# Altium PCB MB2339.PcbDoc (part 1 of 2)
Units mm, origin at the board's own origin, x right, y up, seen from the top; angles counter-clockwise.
Board outline 43 x 47 mm, 4 copper layers (Top Layer, Signal Layer 1, Signal Layer 2, Bottom Layer), stack 1.539 mm thick; 100 components, 80 nets, 370 pads, 542 vias.
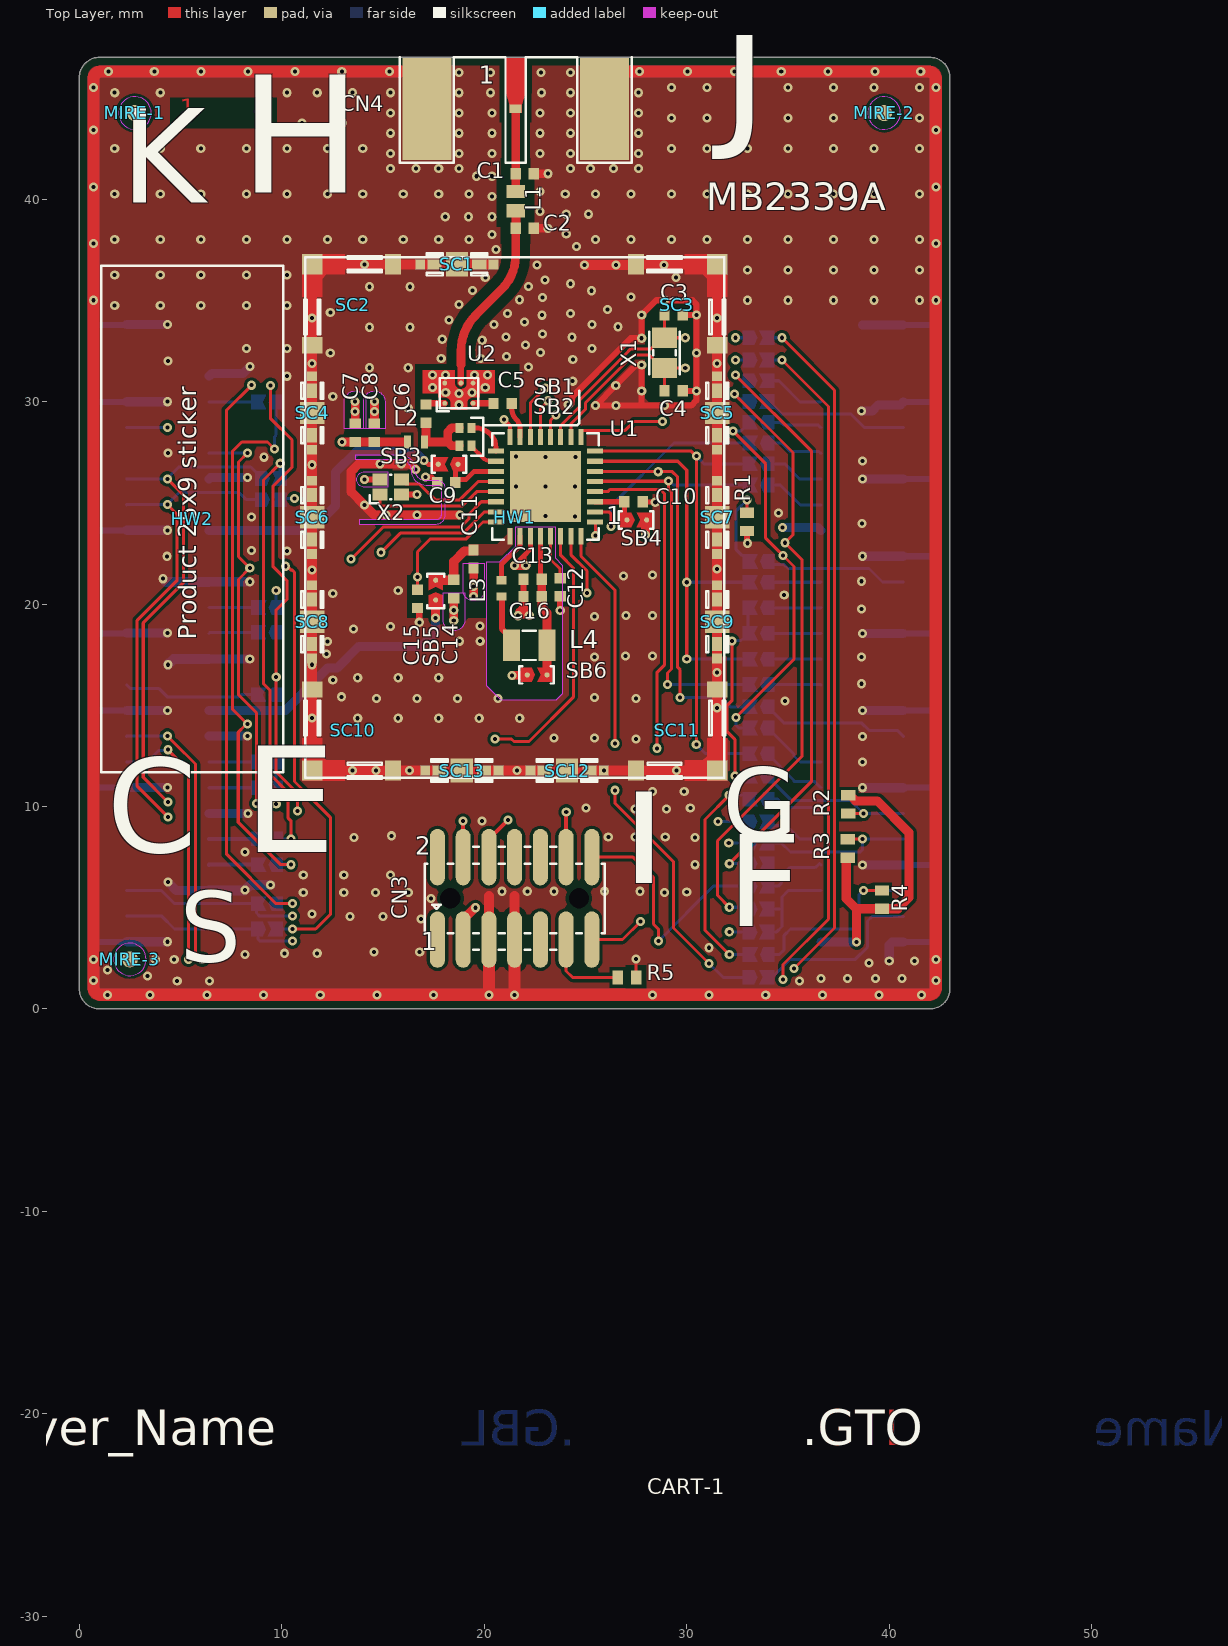
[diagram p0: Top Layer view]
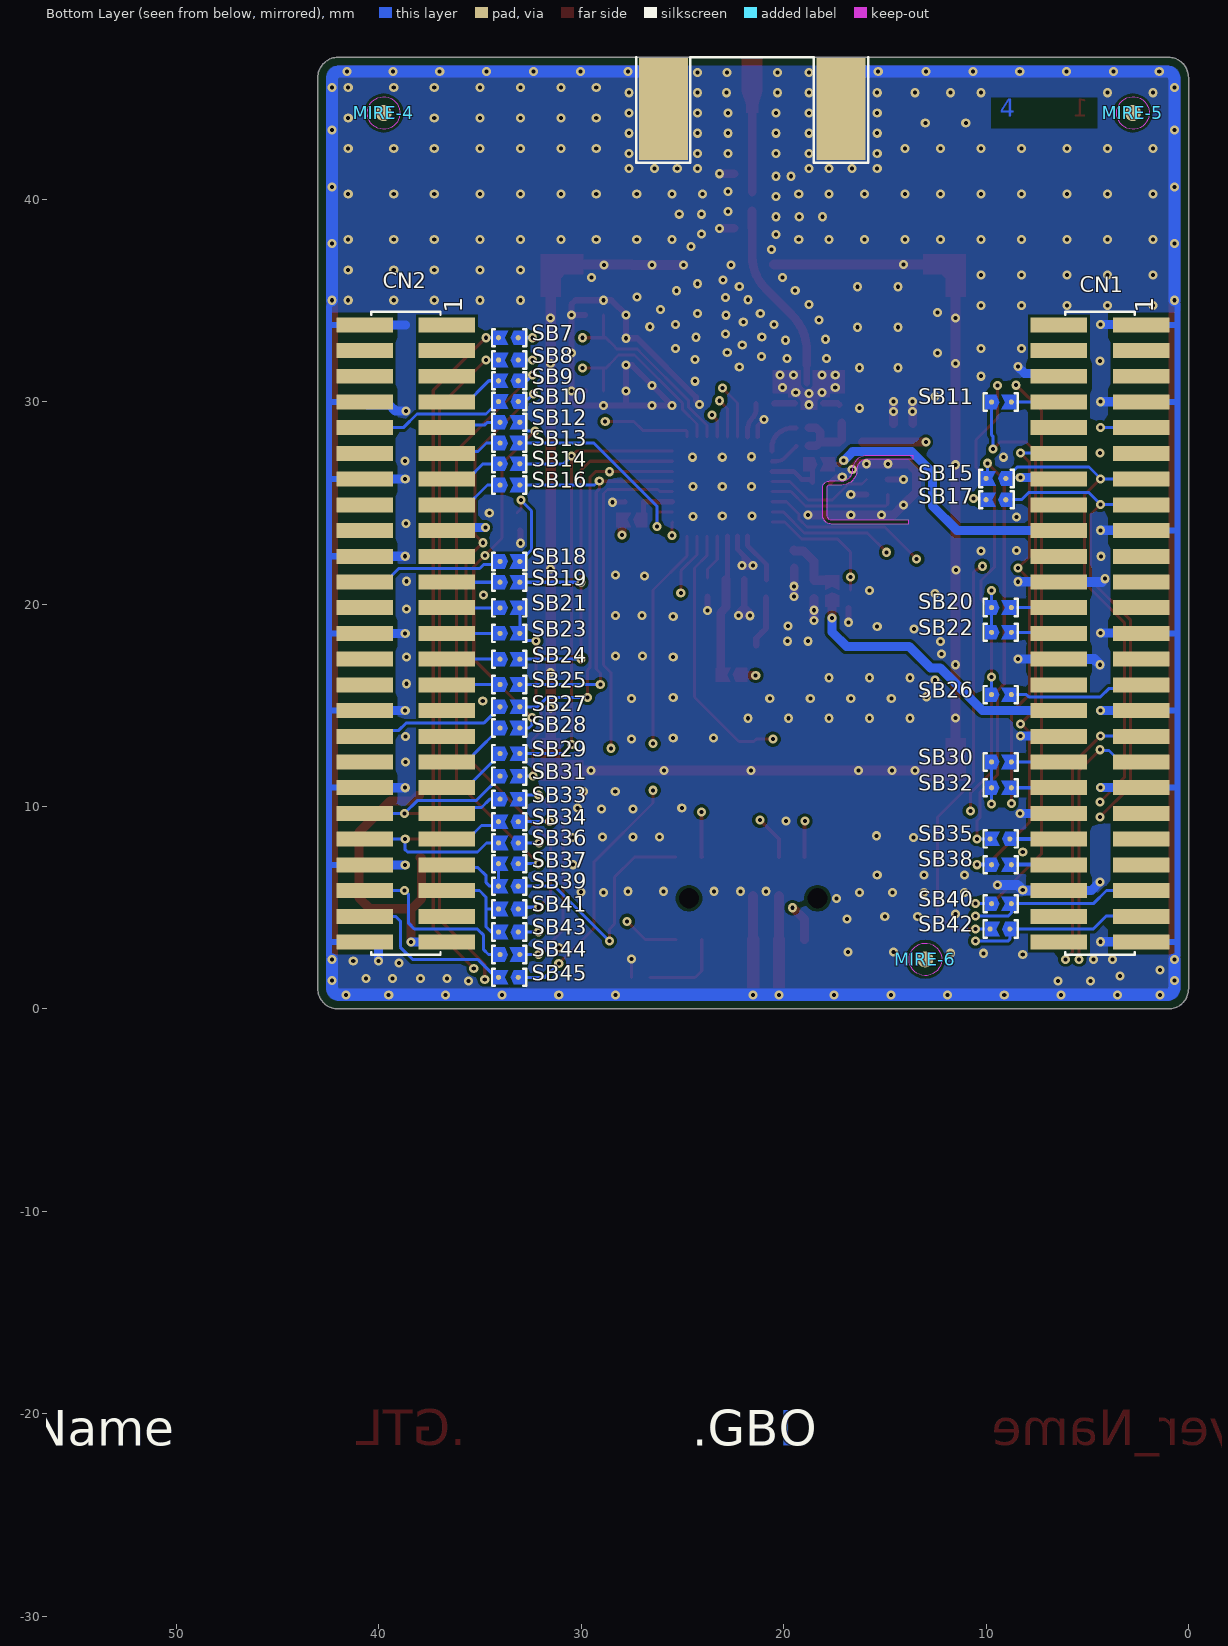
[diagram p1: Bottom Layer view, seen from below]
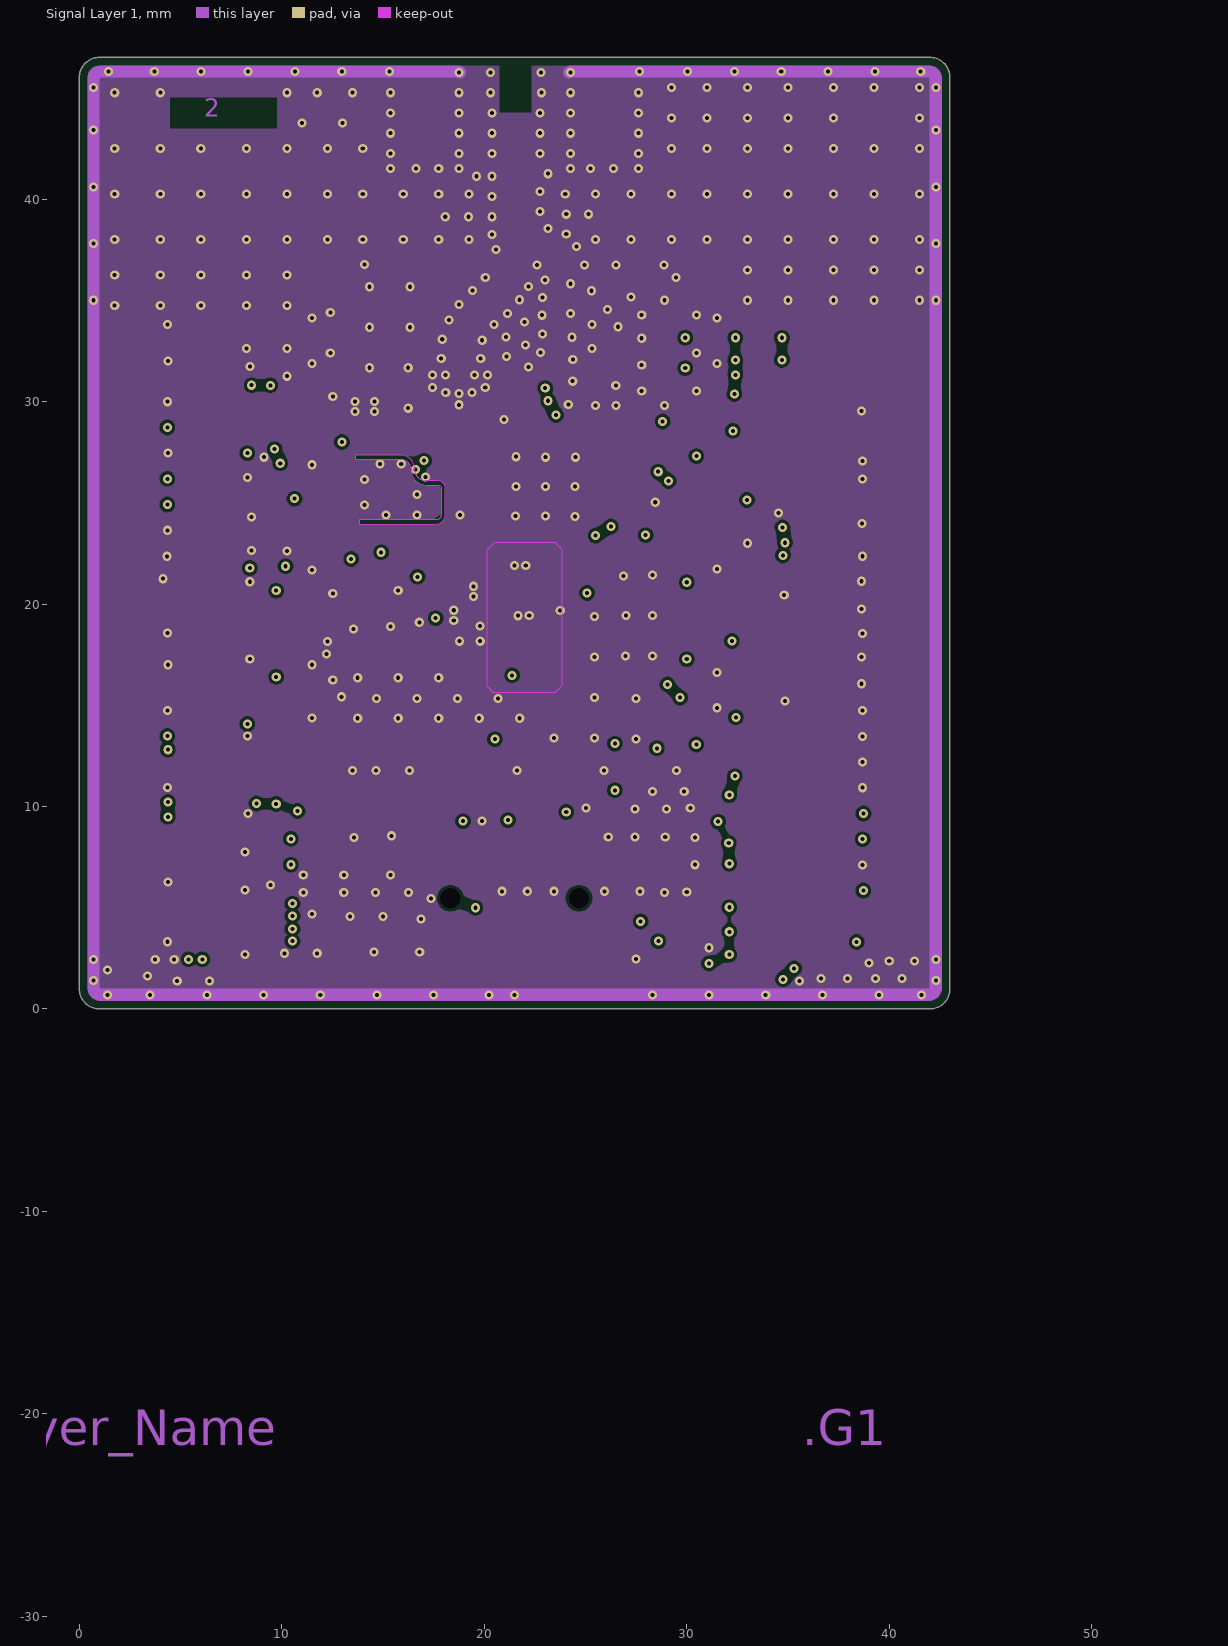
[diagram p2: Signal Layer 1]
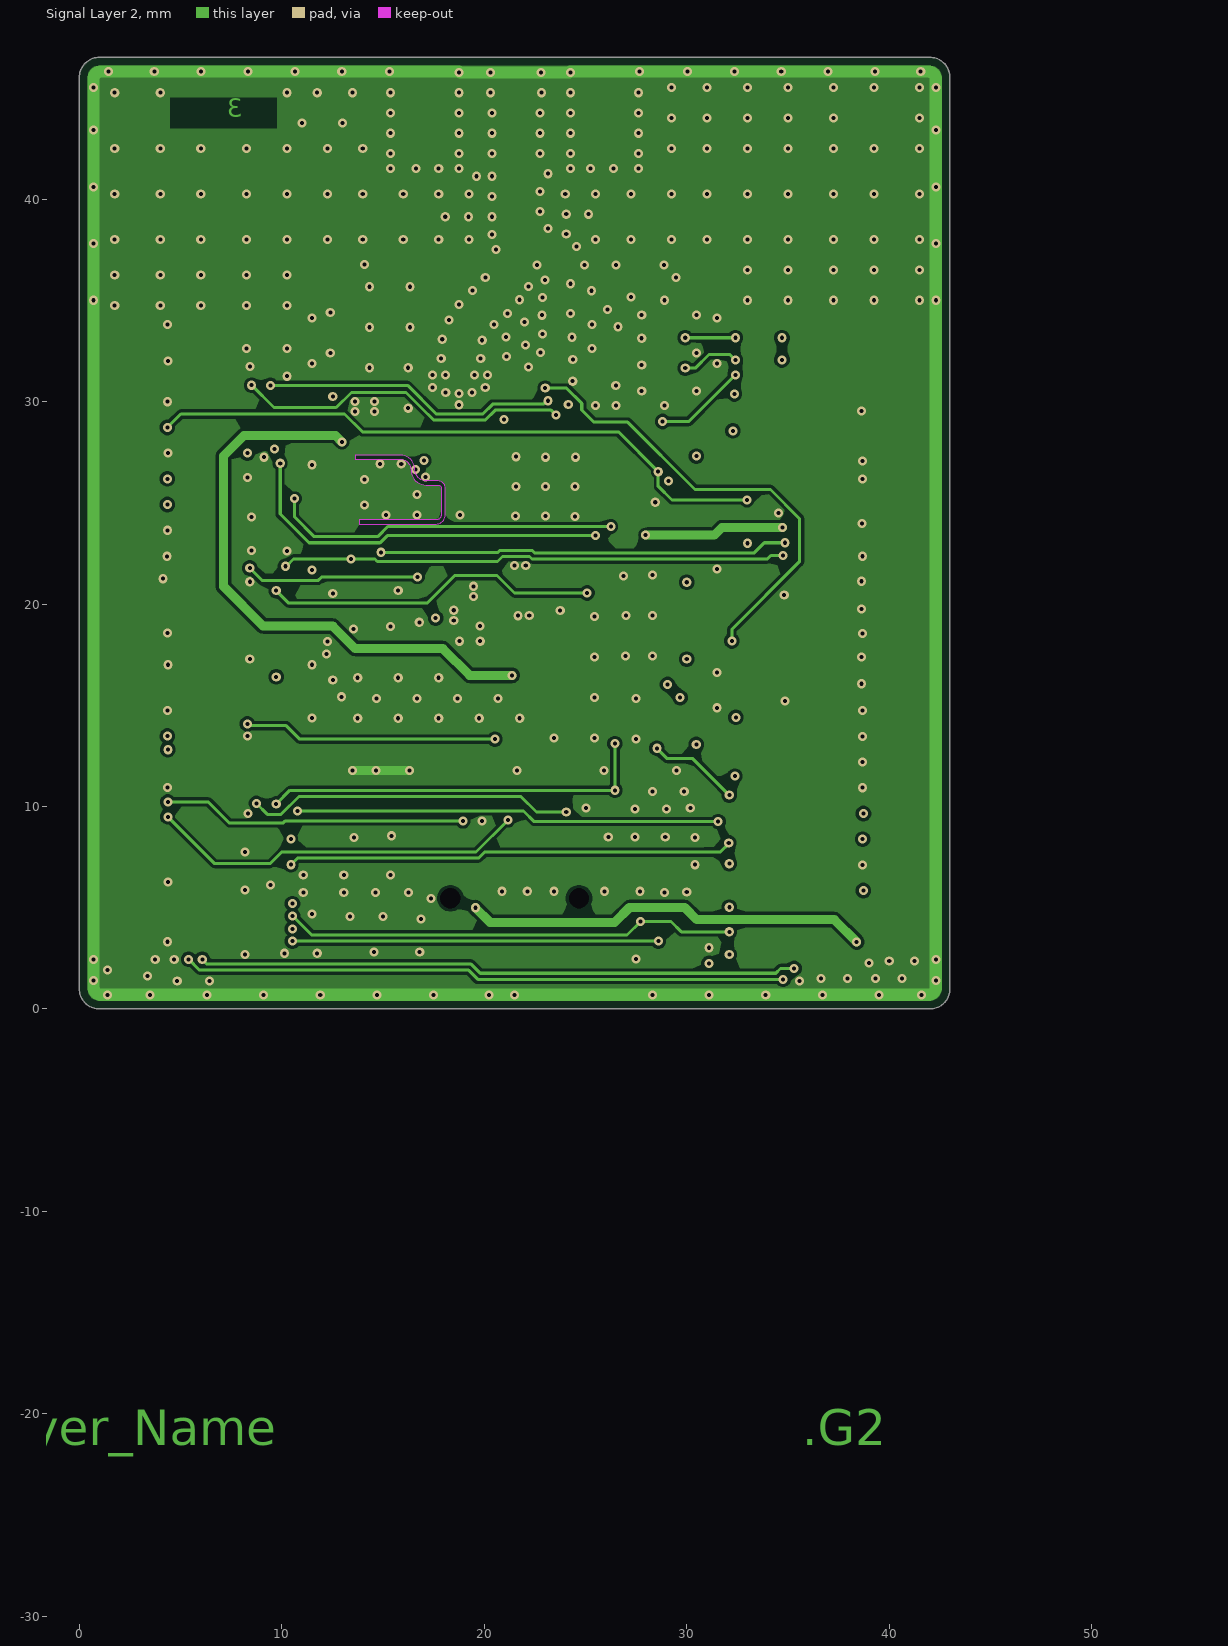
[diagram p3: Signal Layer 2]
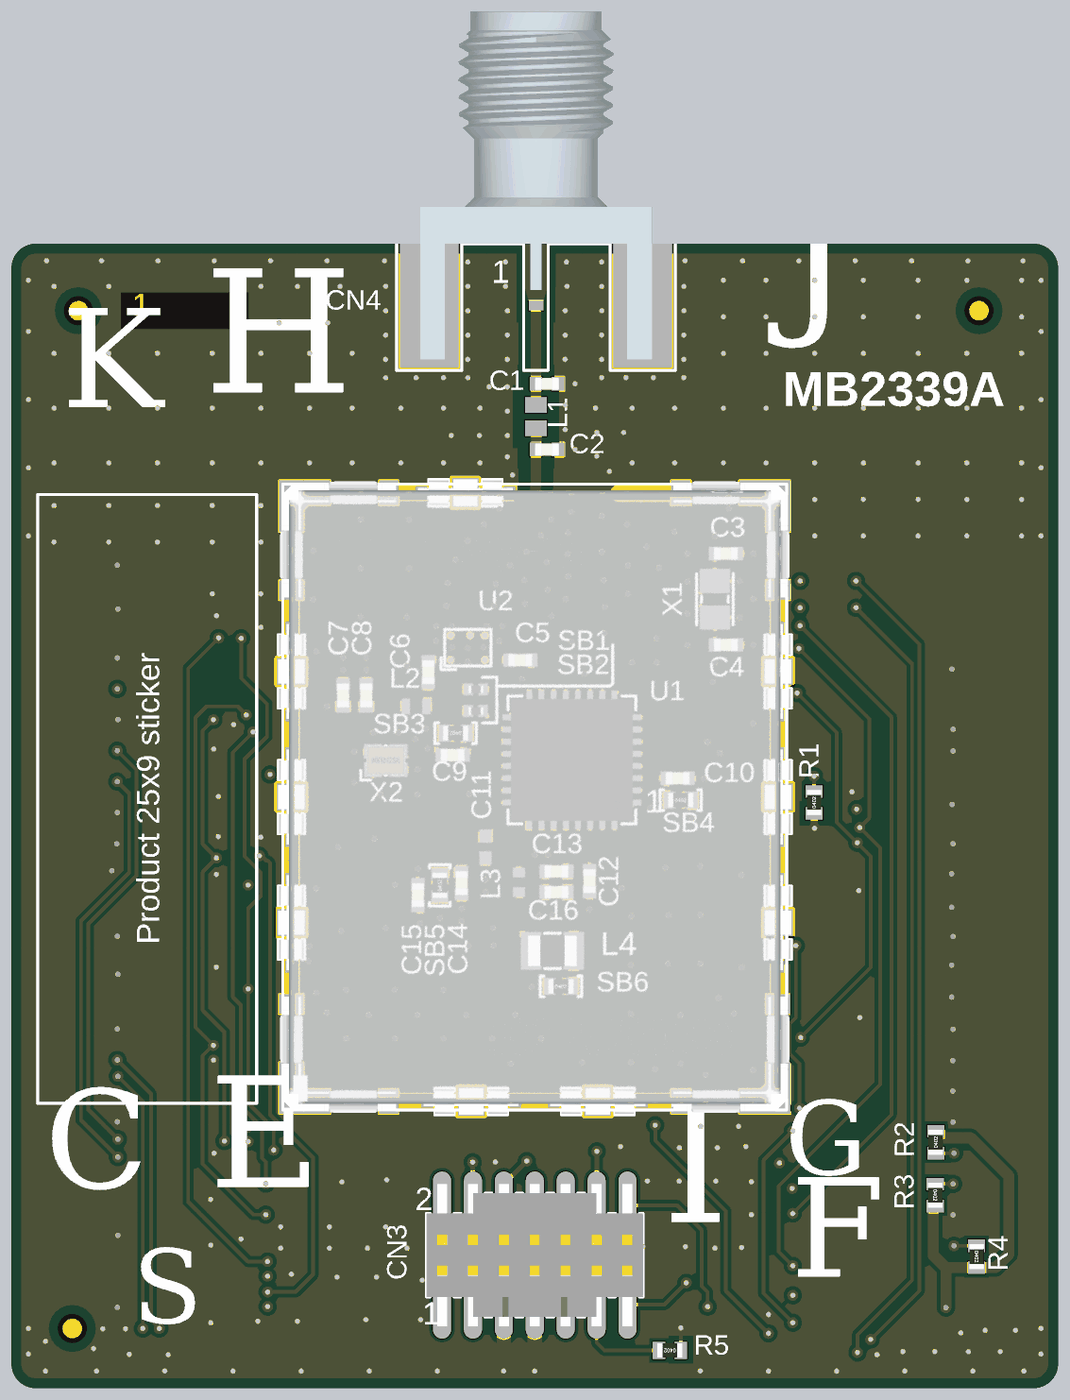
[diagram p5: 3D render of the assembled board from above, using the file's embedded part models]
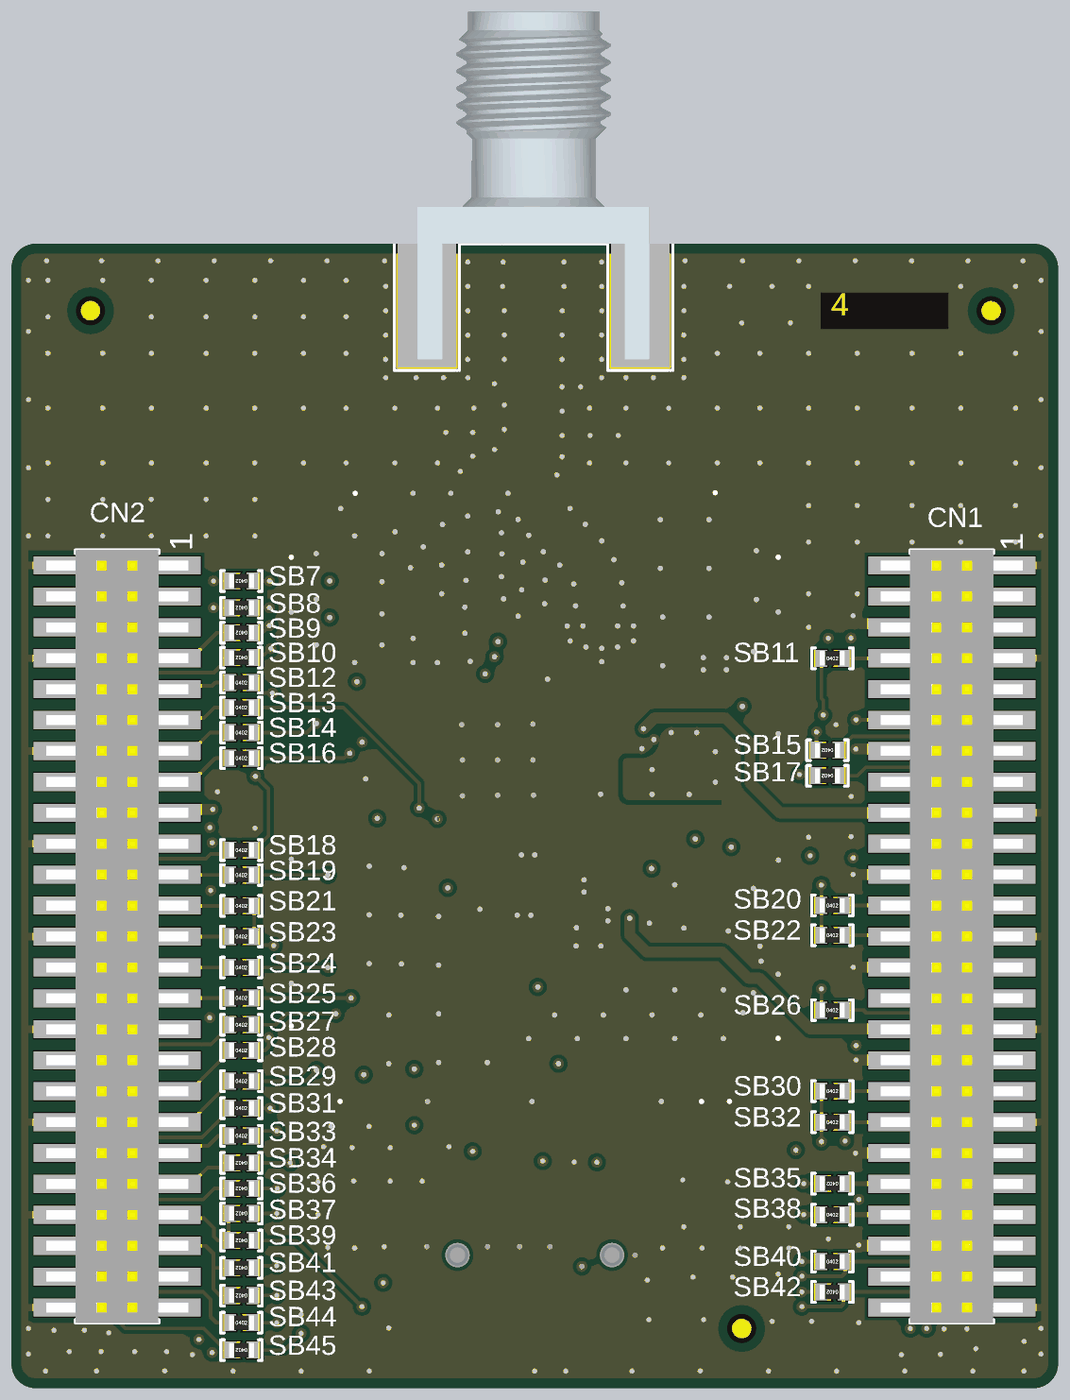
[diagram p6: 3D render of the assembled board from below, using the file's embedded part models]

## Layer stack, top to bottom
Top Solder: solder mask 0.015, Solder Resist, Dk 3.5
Top Layer: signal copper 0.0406
Dielectric 1: core 0.254, Core-028, Dk 4.4
Signal Layer 1: signal copper 0.0178
Dielectric 2: core 0.9144, FR4, Dk 4.4
Signal Layer 2: signal copper 0.0178
Dielectric 3: core 0.254, Core-028, Dk 4.4
Bottom Layer: signal copper 0.0406
Bottom Solder: solder mask 0.015, Solder Resist, Dk 3.5

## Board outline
0,1 ccw(c1,1) 1,0 42,0 ccw(c42,1) 43,1 43,46 ccw(c42,46) 42,47 1,47 ccw(c1,46) 0,46

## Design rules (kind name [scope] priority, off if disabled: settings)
BoardOutlineClearance [All] p1: gap=0.4 ignorepadtopadclearanceinfootprint=FALSE
Clearance [touchesRoom('RoomDefinition_1')] p1: gap=0.095 ignorepadtopadclearanceinfootprint=FALSE
Clearance Clearance_IPD [WithinRoom('RoomDefinition_IPD') vs OnLayer('Top Layer')] p2: gap=0.138 ignorepadtopadclearanceinfootprint=FALSE
Clearance Clearance_Keepout [All vs IsKeepOut] p3: gap=0.15 ignorepadtopadclearanceinfootprint=TRUE except(0: Poly-Region)
Clearance Clearance_RF-50R [InNetClass('NC_RF-50R')] p4: gap=0.5 ignorepadtopadclearanceinfootprint=FALSE except(0.15: Arc-Arc Arc-Track Arc-SMDPad Arc-Via Track-Track Track-SMDPad Track-Via SMDPad-Via Via-Via Via-Fill Via-Region Via-Text Via-Hole; 0.2: SMDPad-SMDPad; 0.3: Poly-Region)
Clearance Clearance_Default_Same-net_GND [InNet('GND')] p5: gap=0.15 ignorepadtopadclearanceinfootprint=TRUE except(0: SMDPad-Via SMDPad-Hole Via-Via; 0.1: Arc-SMDPad Track-SMDPad Via-Hole; 0.12: SMDPad-SMDPad)
Clearance Clearance_Default_Same-net [All] p6: gap=0.15 ignorepadtopadclearanceinfootprint=TRUE except(0.1: Via-Via; 0.12: Arc-SMDPad Track-SMDPad SMDPad-SMDPad)
Clearance Clearance_Default [All] p7: gap=0.15 ignorepadtopadclearanceinfootprint=FALSE
ComponentClearance [All] p1: gap=0.165 collisioncheckmode=3 verticalgap=0.165 showdistances=TRUE
HoleSize [All] p1: absolutevalues=TRUE maxlimit=10 minlimit=0.025 maxpercent=80.000 minpercent=20.000
MinimumSolderMaskSliver [All] p1: minsoldermaskwidth=0.1
PlaneConnect [All] p1: planeconnectstyle=Relief reliefexpansion=0.508 reliefentries=4 reliefconductorwidth=0.21 reliefairgap=0.21
PolygonConnect [HasFootprint('STM32WL33_IPD') vs OnTopLayer] p1: connectstyle=Direct reliefconductorwidth=0.254 reliefentries=4 polygonreliefangle="90 Angle" airgapwidth=0.254
PolygonConnect PolygonConnect_CLIP [TouchesRoom('RoomDefinition')or TouchesRoom('RoomDefinition_2') or   TouchesRoom('RoomDefinition_3')] p2: connectstyle=Direct reliefconductorwidth=0.254 reliefentries=4 polygonreliefangle="90 Angle" airgapwidth=0.254
PolygonConnect PolygonConnect_Default [All] p3: thpad.connectstyle=Direct thpad.reliefconductorwidth=0.3 thpad.reliefentries=4 thpad.polygonreliefangle="90 Angle" thpad.airgapwidth=0.25 smdpad.connectstyle=NoConnect smdpad.reliefconductorwidth=0.254 smdpad.reliefentries=4 smdpad.polygonreliefangle="90 Angle" smdpad.airgapwidth=0.254 via.connectstyle=Direct via.reliefconductorwidth=0.254 via.reliefentries=4 via.polygonreliefangle="90 Angle" via.airgapwidth=0.254
RoomDefinition RoomDefinition_IPD [False vs False] p1: confinementstyle=ConfineIn formatcopy=TRUE lockcomponents=FALSE outline 16.675,31.8 20.893,31.8 20.893,29.463 16.675,29.463
RoutingVias RoutingVias_Default [All] p1 off: holewidth=0.3 width=0.6 viastyle="Through Hole" minholewidth=0.3 minwidth=0.6 maxholewidth=0.3 maxwidth=0.6 useviatemplates=TRUE viatemplateguid#1={AA9A79F4-FA52-4FAE-B866-08D9C0E7A464} viatemplatename#1=v45h20m0mx0
SilkToSilkClearance [All] p1 off: silktosilkclearance=0.2
SilkToSolderMaskClearance [IsPad] p1 off: minsilkscreentomaskgap=0.2 clearancetoexposedcopper=TRUE
SolderMaskExpansion [All] p1: expansion=0.102 istentingtop=FALSE
SupplyNets "Schematic Supply Nets_4" [InNet('GND')] p1: voltage=0.000
SupplyNets "Schematic Supply Nets_3" [InNet('VDD')] p2: voltage=0.000
SupplyNets "Schematic Supply Nets_2" [InNet('VDDRF')] p3: voltage=0.000
SupplyNets "Schematic Supply Nets_1" [InNet('VFBSD')] p4: voltage=0.000
SupplyNets "Schematic Supply Nets" [InNet('VDDSD')] p5: voltage=0.000
ViasUnderSMD [InPadClass('PC__VIAS-IN-PAD')] p1: allowed=TRUE
Width Width_RF-50R [InNetClass('NC_RF-50R')] p1: maxlimit=0.43 minlimit=0.25 preferedwidth=0.254 toplayer_prefwidth=0.43 impedanceprofiledriven=TRUE impedanceprofileid={AD1550EC-3D0E-4E34-9E21-FD44D1EEEC04} impedanceprofilevalue=50.000000 minimp=50.000000 maximp=50.000000 favimp=50.000000
Width Width_Default [All] p2: maxlimit=10 minlimit=0.15 preferedwidth=0.2
24 further rules are at their usual default settings.

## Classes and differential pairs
component class Designator: C9 C10 C11 C12 C13 C14 CN3 L4
pad class PC__VIAS-IN-PAD: U1-49
net class NC_RF-50R: NetC1_2 NetC2_2

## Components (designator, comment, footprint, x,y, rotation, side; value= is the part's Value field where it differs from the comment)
C1 "Capacitor" C0402 22,41.25 r180 top value=1pF
C2 "Capacitor" C0402 22,38.55 r180 top value=1pF
C3 "Capacitor" C0402 29.35,34.275 r180 top value=6.8pF (schematic designator C9)
C4 "Capacitor" C0402 29.35,30.525 r0 top value=6.8pF (schematic designator C13)
C5 "Capacitor" C0402 20.906,29.902 r180 top value=100pF (schematic designator C7)
C6 "Capacitor" C0402 17.125,29.405 r270 top value=100pF (schematic designator C5)
C7 "Capacitor" C0402 13.625,28.45 r90 top value=100pF (schematic designator C14)
C8 "Capacitor" C0402 14.575,28.45 r270 top value=100nF (schematic designator C15)
C9 "Capacitor" C0402 18.125,26 r0 top value=100nF (schematic designator C16)
C10 "Capacitor" C0402 27.37,25.05 r180 top value=100nF (schematic designator C17)
C11 "Capacitor" C0402_H0P5 19.475,22.225 r270 top value=22pF (schematic designator C19)
C12 "Capacitor" C0402 23.75,20.825 r90 top value=220nF (schematic designator C21)
C13 "Capacitor" C0402 22.391,21.222 r0 top value=4.7uF (schematic designator C22)
C14 "Capacitor" C0402 18.493,20.741 r90 top value=4.7uF (schematic designator C18)
C15 "Capacitor" C0402 16.7,20.25 r90 top value=100nF (schematic designator C20)
C16 "Capacitor" C0402 22.391,20.372 r180 top value=100nF (schematic designator C23)
CART-1 "Comment" Sheetbox_4L2S -14.991,-33.827 r0 top
CN1 "Header 25x2" CON_SAMTEC_FTSH-125-02-L-DV_INV 4.366,18.548 r270 bottom locked
CN2 "Header 25x2" CON_SAMTEC_FTSH-125-02-L-DV_INV 38.656,18.548 r270 bottom locked
CN3 "Header 7x2" CON_SAMTEC_FTSH-107-01-L-DV-K-A 21.5,5.465 r0 top
CN4 "mmcx" CON_SMA-RF_CINCH_142-0701-851 21.55,47 r0 top value=Jack_SMA_142-0701-851
HW1 "S02-20150300" SHIELD_HARWIN_S02-25200300_20X25_H3 21.5,24.275 r0 top locked value=S02-25200300R
HW2 "STICKER_PRODUCT" STICKER_PRODUCT_25X9 5.575,24.2 r90 top value=Sticker
L1 "Inductor" IND_0402_MURATA_LQW15AN_H0P5 21.55,39.9 r90 top value=0R
L2 "Inductor" IND_0402_MURATA_LQW15ANXXXX00_H0P5 16.625,28 r0 top value=12nH (schematic designator L8)
L3 "Inductor" IND_0402_MURATA_LQG15HSXXXX02_H0P5 20.85,20.775 r90 top value=100nH (schematic designator L9)
L4 "Inductor" IND_0805_MURATA_LQM21 22.225,17.959 r180 top value=10uH (schematic designator L10)
MIRE-1 "Comment" MIRE_PLACE_SMD_0P8MM 2.75,44.25 r0 top
MIRE-2 "Comment" MIRE_PLACE_SMD_0P8MM 39.75,44.25 r0 top
MIRE-3 "Comment" MIRE_PLACE_SMD_0P8MM 2.5,2.45 r0 top
MIRE-4 "Comment" MIRE_PLACE_SMD_0P8MM 39.75,44.25 r180 bottom
MIRE-5 "Comment" MIRE_PLACE_SMD_0P8MM 2.75,44.25 r180 bottom
MIRE-6 "Comment" MIRE_PLACE_SMD_0P8MM 13,2.45 r180 bottom
R1 "Resistor" R0402 32.975,24.055 r90 top value=100K (schematic designator R2)
R2 "Resistor" R0402 37.975,10.1 r90 top value=10K (schematic designator R1)
R3 "Resistor" R0402 37.95,7.925 r270 top value=10K (schematic designator R9)
R4 "Resistor" R0402 39.65,5.4 r270 top value=10K (schematic designator R10)
R5 "Resistor" R0402 27.05,1.55 r180 top value=100R (schematic designator R8)
SB1 "SB_ON" SOLDER-BRIDGE_R0201_0R 19.075,28.7 r180 top value=0R
SB2 "SB_ON" SOLDER-BRIDGE_R0201_0R 19.073,27.813 r180 top value=0R
SB3 "SB_ON" SOLDER-BRIDGE_R0402-0R 18.25,26.9 r180 top value=0R (schematic designator SB40)
SB4 "SB_ON" SOLDER-BRIDGE_R0402-0R 27.495,24.15 r0 top value=0R (schematic designator SB42)
SB5 "SB_ON" SOLDER-BRIDGE_R0402-0R 17.6,20.65 r90 top value=0R (schematic designator SB39)
SB6 "SB_ON" SOLDER-BRIDGE_R0402-0R 22.575,16.5 r0 top value=0R (schematic designator SB41)
SB7 "SB_ON" SOLDER-BRIDGE_R0402-0R 33.55,33.15 r0 bottom value=0R (schematic designator SB3)
SB8 "SB_ON" SOLDER-BRIDGE_R0402-0R 33.55,32.05 r0 bottom value=0R (schematic designator SB4)
SB9 "SB_ON" SOLDER-BRIDGE_R0402-0R 33.55,31.025 r0 bottom value=0R (schematic designator SB29)
SB10 "SB_ON" SOLDER-BRIDGE_R0402-0R 33.55,30 r0 bottom value=0R (schematic designator SB5)
SB11 "SB_ON" SOLDER-BRIDGE_R0402-0R 9.275,29.975 r180 bottom value=0R (schematic designator SB46)
SB12 "SB_ON" SOLDER-BRIDGE_R0402-0R 33.55,28.975 r180 bottom value=0R (schematic designator SB24)
SB13 "SB_ON" SOLDER-BRIDGE_R0402-0R 33.55,27.95 r180 bottom value=0R (schematic designator SB28)
SB14 "SB_ON" SOLDER-BRIDGE_R0402-0R 33.55,26.925 r180 bottom value=0R (schematic designator SB33)
SB15 "SB_ON" SOLDER-BRIDGE_R0402-0R 9.475,26.2 r0 bottom value=0R (schematic designator SB6)
SB16 "SB_ON" SOLDER-BRIDGE_R0402-0R 33.55,25.875 r180 bottom value=0R (schematic designator SB35)
SB17 "SB_ON" SOLDER-BRIDGE_R0402-0R 9.475,25.15 r0 bottom value=0R (schematic designator SB27)
SB18 "SB_ON" SOLDER-BRIDGE_R0402-0R 33.55,22.1 r180 bottom value=0R (schematic designator SB45)
SB19 "SB_ON" SOLDER-BRIDGE_R0402-0R 33.55,21.075 r180 bottom value=0R (schematic designator SB34)
SB20 "SB_ON" SOLDER-BRIDGE_R0402-0R 9.275,19.825 r180 bottom value=0R (schematic designator SB22)
SB21 "SB_ON" SOLDER-BRIDGE_R0402-0R 33.55,19.808 r180 bottom value=0R (schematic designator SB30)
SB22 "SB_ON" SOLDER-BRIDGE_R0402-0R 9.275,18.6 r180 bottom value=0R (schematic designator SB23)
SB23 "SB_ON" SOLDER-BRIDGE_R0402-0R 33.55,18.55 r180 bottom value=0R (schematic designator SB32)
SB24 "SB_ON" SOLDER-BRIDGE_R0402-0R 33.55,17.275 r180 bottom value=0R (schematic designator SB21)
SB25 "SB_ON" SOLDER-BRIDGE_R0402-0R 33.55,16.025 r180 bottom value=0R (schematic designator SB36)
SB26 "SB_ON" SOLDER-BRIDGE_R0402-0R 9.275,15.525 r180 bottom value=0R (schematic designator SB25)
SB27 "SB_ON" SOLDER-BRIDGE_R0402-0R 33.55,14.925 r180 bottom value=0R (schematic designator SB44)
SB28 "SB_ON" SOLDER-BRIDGE_R0402-0R 33.55,13.875 r180 bottom value=0R (schematic designator SB37)
SB29 "SB_ON" SOLDER-BRIDGE_R0402-0R 33.55,12.612 r180 bottom value=0R (schematic designator SB17)
SB30 "SB_ON" SOLDER-BRIDGE_R0402-0R 9.275,12.2 r180 bottom value=0R (schematic designator SB26)
SB31 "SB_ON" SOLDER-BRIDGE_R0402-0R 33.55,11.5 r180 bottom value=0R
SB32 "SB_ON" SOLDER-BRIDGE_R0402-0R 9.275,10.925 r180 bottom value=0R (schematic designator SB12)
SB33 "SB_ON" SOLDER-BRIDGE_R0402-0R 33.55,10.362 r180 bottom value=0R (schematic designator SB8)
SB34 "SB_ON" SOLDER-BRIDGE_R0402-0R 33.55,9.25 r0 bottom value=0R (schematic designator SB10)
SB35 "SB_ON" SOLDER-BRIDGE_R0402-0R 9.275,8.4 r0 bottom value=0R (schematic designator SB38)
SB36 "SB_ON" SOLDER-BRIDGE_R0402-0R 33.55,8.2 r0 bottom value=0R (schematic designator SB43)
SB37 "SB_ON" SOLDER-BRIDGE_R0402-0R 33.55,7.175 r0 bottom value=0R (schematic designator SB13)
SB38 "SB_ON" SOLDER-BRIDGE_R0402-0R 9.275,7.125 r180 bottom value=0R (schematic designator SB20)
SB39 "SB_ON" SOLDER-BRIDGE_R0402-0R 33.55,6.062 r0 bottom value=0R (schematic designator SB47)
SB40 "SB_ON" SOLDER-BRIDGE_R0402-0R 9.275,5.2 r180 bottom value=0R (schematic designator SB14)
SB41 "SB_ON" SOLDER-BRIDGE_R0402-0R 33.55,4.938 r0 bottom value=0R (schematic designator SB15)
SB42 "SB_ON" SOLDER-BRIDGE_R0402-0R 9.275,3.95 r0 bottom value=0R (schematic designator SB16)
SB43 "SB_ON" SOLDER-BRIDGE_R0402-0R 33.55,3.8 r0 bottom value=0R (schematic designator SB49)
SB44 "SB_ON" SOLDER-BRIDGE_R0402-0R 33.55,2.688 r180 bottom value=0R (schematic designator SB18)
SB45 "SB_ON" SOLDER-BRIDGE_R0402-0R 33.55,1.562 r0 bottom value=0R (schematic designator SB19)
SC1 "Shield-clip_S0951-46R" CLIP_HARWIN_S0951-46R 18.65,36.775 r180 top value=S0951-46R
SC2 "Shield-clip_S0951-46R" CLIP_HARWIN_S0981-46R 11.5,36.775 r180 top value=S0981-46R
SC3 "Shield-clip_S0951-46R" CLIP_HARWIN_S0981-46R 31.5,36.775 r90 top value=S0981-46R
SC4 "Shield-clip_S0951-46R" CLIP_HARWIN_S0951-46R 11.5,29.433 r90 top value=S0951-46R
SC5 "Shield-clip_S0951-46R" CLIP_HARWIN_S0951-46R 31.5,29.433 r90 top value=S0951-46R
SC6 "Shield-clip_S0951-46R" CLIP_HARWIN_S0951-46R 11.5,24.278 r90 top value=S0951-46R (schematic designator SC11)
SC7 "Shield-clip_S0951-46R" CLIP_HARWIN_S0951-46R 31.5,24.278 r270 top value=S0951-46R (schematic designator SC12)
SC8 "Shield-clip_S0951-46R" CLIP_HARWIN_S0951-46R 11.5,19.12 r90 top value=S0951-46R (schematic designator SC9)
SC9 "Shield-clip_S0951-46R" CLIP_HARWIN_S0951-46R 31.5,19.12 r90 top value=S0951-46R (schematic designator SC10)
SC10 "Shield-clip_S0951-46R" CLIP_HARWIN_S0981-46R 11.5,11.775 r270 top value=S0981-46R (schematic designator SC6)
SC11 "Shield-clip_S0951-46R" CLIP_HARWIN_S0981-46R 31.5,11.775 r0 top value=S0981-46R (schematic designator SC7)
SC12 "Shield-clip_S0951-46R" CLIP_HARWIN_S0951-46R 24.09,11.775 r0 top value=S0951-46R (schematic designator SC13)
SC13 "Shield-clip_S0951-46R" CLIP_HARWIN_S0951-46R 18.89,11.774 r180 top value=S0951-46R (schematic designator SC8)
U1 "IC_STM32WL3R" ICC_VFQFPN32-EPAD_5X5_P050 23.025,25.8 r90 top value=STM32WL3RKBV6
U2 "MLPF-WL-0xD3" ICC_CSPG5_1P5X1P9_P060 18.748,30.411 r90 top value=MLPF-WL-01D3
X1 "XTAL_2_PINS" CRY_NX2012SA_2P 28.9,32.4 r270 top value=32.768kHz
X2 "XTAL_4_PINS" CRY_NX1612SA_4P 15.38,25.775 r0 top locked value=48MHz

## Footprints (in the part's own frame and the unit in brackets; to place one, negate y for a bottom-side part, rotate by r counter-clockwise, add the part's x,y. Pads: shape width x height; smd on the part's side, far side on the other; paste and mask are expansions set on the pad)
C0402 [mm]
  rect 0.51x0.56 smd mask+0.05: 1(-0.45,0) 2(0.45,0)
  body extent -0.5,-0.3 0.5,0.3, height 0.4
C0402_H0P5 [mm] "MCD-03898"
  rect 0.55x0.5 smd mask+0.05: 1(-0.45,0) 2(0.45,0)
  body extent -0.53,-0.28 0.53,0.27, height 0.55
CLIP_HARWIN_S0951-46R [mm] "MCD-01587_CLIP-X1"
  rect 0.48x0.5 smd mask+0.1: 1(-1.81,0) 1(1.81,0)
  rect 0.7x0.5 smd mask+0.1: 1(-1.1,0) 1(1.1,0)
  rect 1.1x1.2 smd mask+0.1: 1(0,0)
  silkscreen extent -1.5,-0.55 1.5,0.55, body extent -2.05,-0.65 2.05,0.65, height 1.28
CLIP_HARWIN_S0981-46R [mm] "MCD-02164"
  rect 0.8x1 smd mask+0.05: 1(-4,0)
  rect 1x0.8 smd mask+0.05: 1(0,4)
  rect 1x1 smd mask+0.05: 1(0,0)
  Top Layer region: -1.6,-0.5 0.5,-0.5 0.5,1.6 -0.5,1.6 -0.5,0.7 -0.7,0.5 -1.6,0.5
  silkscreen extent -3.45,-0.4 0.4,3.45, body extent -4.3,-0.46 0.46,4.3, height 1.4
CON_SAMTEC_FTSH-107-01-L-DV-K-A [mm] "MCD-01959"
  oval 0.74x2.79 smd mask+0.05: 1(-3.81,-2.035) 2(-3.81,2.035) 3(-2.54,-2.035) 4(-2.54,2.035) 5(-1.27,-2.035) 6(-1.27,2.035) 7(0,-2.035) 8(0,2.035) 9(1.27,-2.035) 10(1.27,2.035) 11(2.54,-2.035) 12(2.54,2.035) 13(3.81,-2.035) 14(3.81,2.035)
  round 0 hole 1 unplated paste-2539.97 mask+0.05: NPTH1(-3.175,0) NPTH2(3.175,0)
  silkscreen extent -4.44,-2.54 4.44,2.54, body extent -4.44,-2.92 4.45,2.92, height 6.12
CON_SAMTEC_FTSH-125-02-L-DV_INV [mm]
  rect 0.74x2.79 smd mask+0.05: 1(-15.24,2.035) 2(-15.24,-2.035) 3(-13.97,2.035) 4(-13.97,-2.035) 5(-12.7,2.035) 6(-12.7,-2.035) 7(-11.43,2.035) 8(-11.43,-2.035) 9(-10.16,2.035) 10(-10.16,-2.035) 11(-8.89,2.035) 12(-8.89,-2.035) 13(-7.62,2.035) 14(-7.62,-2.035) 15(-6.35,2.035) 16(-6.35,-2.035) 17(-5.08,2.035) 18(-5.08,-2.035) 19(-3.81,2.035) 20(-3.81,-2.035) 21(-2.54,2.035) 22(-2.54,-2.035) 23(-1.27,2.035) 24(-1.27,-2.035) 25(0,2.035) 26(0,-2.035) 27(1.27,2.035) 28(1.27,-2.035) 29(2.54,2.035) 30(2.54,-2.035) 31(3.81,2.035) 32(3.81,-2.035) 33(5.08,2.035) 34(5.08,-2.035) 35(6.35,2.035) 36(6.35,-2.035) 37(7.62,2.035) 38(7.62,-2.035) 39(8.89,2.035) 40(8.89,-2.035) 41(10.16,2.035) 42(10.16,-2.035) 43(11.43,2.035) 44(11.43,-2.035) 45(12.7,2.035) 46(12.7,-2.035) 47(13.97,2.035) 48(13.97,-2.035) 49(15.24,2.035) 50(15.24,-2.035)
  silkscreen extent -15.88,-1.71 15.88,1.71, body extent -15.87,-2.92 15.88,2.92, height 4.82
CON_SMA-RF_CINCH_142-0701-851 [mil] "MCD-02072"
  rect 23.62x15.75 smd mask+1.97: 1(0,-100)
  rect 95x200 smd mask+1.97: 2(172.48,-100) 3(-172.48,-100)
  rect 95x200 smd far side mask+1.97: 4(-172.48,-100) 5(172.48,-100)
  silkscreen extent -225,-205 225,0, body extent -189,-187 189,376, height 161
CRY_NX1612SA_4P [mm] "MCD-02262"
  rect 0.75x0.6 smd mask+0.038: 1(-0.525,-0.375) 2(0.525,-0.375) 3(0.525,0.375) 4(-0.525,0.375)
  silkscreen extent -1.02,-0.8 0.03,0.6, body extent -0.8,-0.6 0.8,0.6, height 0.31
CRY_NX2012SA_2P [mm]
  rect 1x1.25 smd mask+0.05: 1(-0.75,0) 2(0.75,0)
  silkscreen extent -1.05,-0.75 1.05,0.75, body extent -1.05,-0.63 1.05,0.63, height 0.6
ICC_CSPG5_1P5X1P9_P060 [mm] "MCD-03962"
  round 0.24 smd mask+0.05: A1(-0.5,0.7) A3(-0.5,-0.7) B1(0.5,0.7) B2(0.5,-0.1) B3(0.5,-0.7)
  silkscreen extent -0.9,-0.95 0.75,1.1, body extent -0.75,-0.95 0.75,0.95, height 0.69
ICC_VFQFPN32-EPAD_5X5_P050 [mm] "MCD-04005"
  rect 0.25x0.8 smd mask+0.05: 1(-1.75,-2.45) 2(-1.25,-2.45) 3(-0.75,-2.45) 4(-0.25,-2.45) 5(0.25,-2.45) 6(0.75,-2.45) 7(1.25,-2.45) 8(1.75,-2.45) 17(1.75,2.45) 18(1.25,2.45) 19(0.75,2.45) 20(0.25,2.45) 21(-0.25,2.45) 22(-0.75,2.45) 23(-1.25,2.45) 24(-1.75,2.45)
  rect 0.8x0.25 smd mask+0.05: 9(2.45,-1.75) 10(2.45,-1.25) 11(2.45,-0.75) 12(2.45,-0.25) 13(2.45,0.25) 14(2.45,0.75) 15(2.45,1.25) 16(2.45,1.75) 25(-2.45,1.75) 26(-2.45,1.25) 27(-2.45,0.75) 28(-2.45,0.25) 29(-2.45,-0.25) 30(-2.45,-0.75) 31(-2.45,-1.25) 32(-2.45,-1.75)
  rect 3.5x3.5 smd mask+0.05: 33(0,0)
  silkscreen extent -2.63,-2.63 2.63,2.63, body extent -2.5,-2.5 2.5,2.5, height 0.9
IND_0402_MURATA_LQG15HSXXXX02_H0P5 [mm] "MCD-03474"
  rect 0.4x0.5 smd mask+0.05: 1(-0.4,0) 2(0.4,0)
  body extent -0.55,-0.28 0.55,0.28, height 0.55
IND_0402_MURATA_LQW15AN_H0P5 [mm] "MCD-01606"
  rect 0.65x0.9 smd mask+0.05: 1(-0.475,0) 2(0.475,0)
  body extent -0.55,-0.35 0.55,0.35, height 0.6
IND_0402_MURATA_LQW15ANXXXX00_H0P5 [mm] "MCD-03456"
  rect 0.35x0.65 smd mask+0.05: 1(-0.425,0) 2(0.425,0)
  body extent -0.55,-0.35 0.55,0.35, height 0.51
IND_0805_MURATA_LQM21 [mm] "MCD-02317"
  rect 0.85x1.55 smd mask+0.05: 1(-0.875,0) 2(0.875,0)
  silkscreen extent -0.33,-0.72 0.33,0.72, body extent -1.1,-0.72 1.1,0.72, height 1.45
MIRE_PLACE_SMD_0P8MM [mm]
  round 0.8 smd paste-10 mask+0.2: 1(0,0)
  Top Layer keep-out circle w0.01: c0,0 r0.804
R0402 [mm]
  rect 0.51x0.7 smd mask+0.05: 1(-0.45,0) 2(0.45,0)
  body extent -0.52,-0.3 0.52,0.3, height 0.4
Sheetbox_4L2S [mil] "Sheetbox 4 layers / 2 silkscreens"
  round 20 on Mech16: 1(813.78,210.69) 1(2736.9,210.69)
SHIELD_HARWIN_S02-25200300_20X25_H3 [mm] "MCD-03503"
  silkscreen extent -10.35,-12.85 10.35,12.85, body extent -10.1,-12.6 10.1,12.6, height 3.2
SOLDER-BRIDGE_R0201_0R [mm] "MCD-03219"
  rect 0.4x0.5 smd mask+0.05: 1(-0.3,0) 2(0.3,0)
  body extent -0.32,-0.17 0.32,0.17, height 0.26
SOLDER-BRIDGE_R0402-0R [mil] "MCD-01619"
  round 10 smd paste-393.7: 1(-17.72,0) 2(20.67,0)
  Top Layer region: -30.51,-13.78 -30.51,13.78 -8.86,13.78 -2.95,0 -8.86,-13.78
  Top Layer region: 1.48,13.78 8.37,0 1.48,-13.78 30.51,-13.78 30.51,13.78
  silkscreen extent -33,-17 33,17, body extent -20,-12 20,12, height 14
STICKER_PRODUCT_25X9 [mm] "MCD-00547"
  silkscreen extent -12.5,-4.5 12.5,4.5

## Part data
C1 C2: library part MCD-01600, "Capacitor, MLCC, 1pF, 50V, C0G/NP0, +/-0.1pF, 0402, T=0.5mm", Manufacturer=YAGEO, Manufacturer_Part_Number=CC0402BRNPO9BN1R0, Package=0402
C3 C4: library part MCD-03452, "Capacitor, MLCC, 6.8pF, 50V,C0G/NP0, +/-0.05pF, 0402, T=0.5mm", Manufacturer=MURATA, Manufacturer_Part_Number=GJM1555C1H6R8WB01, Package=0402
C5 C6 C7: library part MCD-03446, "Capacitor, MLCC, 100pF, 50V, C0G/NP0, +/-1%, 0402, T=0.5mm", Manufacturer=MURATA, Manufacturer_Part_Number=GCM1555C1H101FA16, Package=0402
C8: library part MCD-03442, "Capacitor, MLCC, 100nF, 25V, X7R, +/-10%, 0402, T=0.5mm", Manufacturer=MURATA, Manufacturer_Part_Number=GRM155R71E104KE14, Package=0402
C9 C10 C16: library part MCD-03442, "Capacitor, MLCC, 100nF, 25V, X7R, +/-10%, 0402, T=0.5mm", Manufacturer=MURATA, Manufacturer_Part_Number=GRM155R71E104KE14D, Package=0402
C11: library part MCD-03948, "Capacitor, MLCC, 22pF, 50V, C0G, +/-5%, 0402, T=0.5mm", Manufacturer=MURATA, Manufacturer_Part_Number=GJM1555C1H220JB01, Package=0402
C12: library part MCD-03077, "Capacitor, MLCC, 220nF, 35V, X6S, +/-10%, 0402, T=0.5mm", Manufacturer=MURATA, Manufacturer_Part_Number=GRM155C8YA224KE01D, Package=0402
C13 C14: library part MCD-03431, "Capacitor, MLCC, 4.7uF, 10V, X5R, +/-20%, 0402, T=0.5mm", Manufacturer=MURATA, Manufacturer_Part_Number=GRM155R61A475MEAAD, Package=0402
C15: library part MCD-00006, "Capacitor, MLCC, 100nF, 16V, X7R, +/-10%, 0402, T=0.5mm", Manufacturer=YAGEO, Manufacturer_Part_Number=CC0402KRX7R7BB104, Package=0402
CART-1: library part MCD-00279
CN1 CN2: library part MCD-02746, "Header, 25x2, 1.27mm, VR, SMD, T=4.83mm", Manufacturer=SAMTEC, Manufacturer_Part_Number=FTSH-125-02-L-DV
CN3: library part MCD-01531, "Header, 7x2, 1.27mm, VR, T=5.97mm, FTSH series STDC14 without Alignment Pin", Manufacturer=SAMTEC, Manufacturer_Part_Number=FTSH-107-01-L-DV-K
CN4: library part MCD-02072, "Jack_SMA, VR, PCB edge, 50R, T=7.92mm", Manufacturer=CINCH, Manufacturer_Part_Number=142-0701-851
HW1: library part MCD-03503, "RFI shield CAN, 25x20x3mm", Manufacturer=HARWIN, Manufacturer_Part_Number=S02-25200300R, Package=25x20x3mm
HW2: library part MCD-00547, "Sticker product, 25x9mm", Manufacturer=N/A, Manufacturer_HQ_COO=Unknown
L1: library part MCD-01937, "Resistor, 0R, 0402, +/-5%, 1/16W", Manufacturer=YAGEO, Manufacturer_Part_Number=RC0402JR-070RL, Package=0402
L2: library part MCD-03456, "Inductor, 12nH, +/-2%, 500mA, 0R14, 0402, T=0.5mm", Manufacturer=MURATA, Manufacturer_Part_Number=LQW15AN12NG00D, Package=0402
L3: library part MCD-03453, "Inductor, 100nH, +/-5%, 200mA, 1R25, 0402, T=0.5mm", Manufacturer=MURATA, Manufacturer_Part_Number=LQG15HSR10J02, Package=0402
L4: library part MCD-02317, "Inductor, 10uH, +/-20%, 100mA, 0R5, 0805, T=1.45mm", Manufacturer=MURATA, Manufacturer_Part_Number=LQM21FN100M80L, Package=0805
R1: library part MCD-00059, "Resistor, 100K, 0402, +/-1%, 1/16W", Manufacturer=YAGEO, Manufacturer_Part_Number=RC0402FR-07100KL, Package=0402
R2 R3 R4: library part MCD-00053, "Resistor, 10K, 0402, +/-1%, 1/16W", Manufacturer=YAGEO, Manufacturer_Part_Number=RC0402FR-0710KL, Package=0402
R5: library part MCD-00067, "Resistor, 100R, 0402, +/- 1%, 1/16W", Manufacturer=YAGEO, Manufacturer_Part_Number=RC0402FR-07100RL, Package=0402
SB1 SB2: library part MCD-03219, "Solder Bridge ON, 0R, 0201, 1/20W", Manufacturer=YAGEO, Manufacturer_Part_Number=RC0201JR-070RL, Package=0201
SB3 SB4 SB5 SB6 SB7 SB8 SB9 SB10 SB11 SB12 SB13 SB14 SB15 SB16 SB17 SB18 SB19 SB20 SB21 SB22 SB23 SB24 SB25 SB26 SB27 SB28 SB29 SB30 SB31 SB32 SB33 SB34 SB35 SB36 SB37 SB38 SB39 SB40 SB41 SB42 SB43 SB44 SB45: library part MCD-01618, "Resistor, 0R, SB0402, 5%, 0.063W", Manufacturer=YAGEO, Manufacturer_Part_Number=RC0402JR-070RL, Package=0402
SC1 SC4 SC5 SC6 SC7 SC8 SC9 SC12 SC13: library part MCD-01587, "RFI shield clip mini TIN SMD", Manufacturer=HARWIN, Manufacturer_Part_Number=S0951-46R, Package=1.1x3.9mm
SC2 SC3 SC10 SC11: library part MCD-02164, "Shield clip Harwin S0981-46R to fix RF shielded cavity", Manufacturer=HARWIN, Manufacturer_Part_Number=S0981-46R, Package=0.8x4.7x1.4mm
U1: library part MCD-04431, "MCU, ARM Cortex-M0 32-bit, 128KB Flash, 16KB SRAM, With Crypto", Manufacturer=STMICROELECTRONICS, Manufacturer_Part_Number=STM32WL3RKBV6, Package=QFN32
U2: library part MCD-03962, "IC, 862 To 928MHz,16dBm, 4L PCB, IPD for STM32WL3", Manufacturer=STMICROELECTRONICS, Manufacturer_Part_Number=MLPF-WL-01D3, Package=CSPG
X1: library part MCD-01445, "Crystal, 32.768kHz, 7pF, +/-20ppm, 80K, 2.05x1.2mm", Manufacturer=NDK, Manufacturer_Part_Number=NX2012SA-32.768KHz-EXS00A-MU00389, Package=2.05x1.2mm
X2: library part MCD-03559, "Crystal, 48MHz, 8pF, +/-10ppm, 80R, 1.6x1.2mm", Manufacturer=NDK, Manufacturer_Part_Number=NX1612SA-48.000MHz-EXS00A-CS12140, Package=1.6x1.2mm

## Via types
v1: diameter 0.45, hole 0.2, Top Layer to Bottom Layer, tented both sides, 542 vias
